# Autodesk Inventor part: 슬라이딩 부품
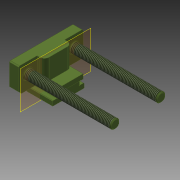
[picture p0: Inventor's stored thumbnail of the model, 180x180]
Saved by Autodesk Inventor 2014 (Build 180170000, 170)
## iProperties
Created: 2017-04
Part Number: 슬라이딩 부품
Material: 강철, 연강
Document SubType Name: Modeling
Designer: mduedu
Density: 7.86 g/cm^3
Appearance: 올리브 녹색
Mass: 390.322 g
Surface Area: 152.125 cm^2
Volume: 49.6593 cm^3
Author: mduedu
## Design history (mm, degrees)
sketch "스케치1"
  geometry: L1 (37, 35)-(10, 35); L2 (0, 17)-(0, 0); L3 (0, 17)-(5, 17); L4 (5, 17)-(5, 12); L5 (5, 12)-(10, 12); L6 (10, 12)-(10, 35); L7 (37, 35)-(37, 0); L8 (37, 0)-(0, 0); L9 (37, -35)-(10, -35); L10 (0, -17)-(0, 0); L11 (0, -17)-(5, -17); L12 (5, -17)-(5, -12); L13 (5, -12)-(10, -12); L14 (10, -12)-(10, -35); L15 (37, -35)-(37, 0)
  constraints: 30 end point, 6 symmetric about line, 3 perpendicular, 2 horizontal, 2 point on line, 2 vertical
  dimensions: "d39" = 5 distance of L2.start L3.end; "d41" = 70 distance between parallel lines of L9 L1; "d42" = 27 distance of L9.start L9.end; "d43" = 24 distance between parallel lines of L13 L5; "d44" = 5 distance of L4.end L5.end; "d45" = 34 distance between parallel lines of L11 L3
extrude "돌출1" new body sketch "스케치1" distance "d5" = 10; taper "d6" = 0 deg
sketch "스케치2"
  geometry: L1 (-35, 10)-(-35, 37) reference; L2 (17, 0)-(-17, 0) reference; L3 (-17, 0)-(-17, 5) reference; L4 (-17, 5)-(-12, 5) reference; L5 (-12, 5)-(-12, 10) reference; L6 (-12, 10)-(-35, 10) reference; L7 (-35, 37)-(35, 37) reference; L8 (35, 37)-(35, 10) reference; L9 (35, 10)-(12, 10) reference; L10 (12, 10)-(12, 5) reference; L11 (12, 5)-(17, 5) reference; L12 (17, 5)-(17, 0) reference; L13 (-12, 10)-(-15, 10); L14 (-15, 10)-(-15, 15); L15 (-15, 15)-(15, 15); L16 (15, 15)-(15, 10); L17 (15, 10)-(12, 10)
  constraints: 10 end point, 4 perpendicular, 2 point on line
  dimensions: "d46" = 3 distance between parallel lines of L14 L5; "d47" = 3 distance between parallel lines of L16 L10 (= d46); "d48" = 5 distance of L13.end L14.end
extrude "돌출2" join sketch "스케치2" distance "d12" = 20; taper "d13" = 0 deg
sketch "스케치3"
  geometry: L1 (0, 20)-(8, 20); L2 (8, 20)-(8, 50); L3 (8, 50)-(0, 50); L4 (0, 50)-(0, 20); L5 (0, 50)-(20, 50) reference; L6 (0, 20)-(20, 20) reference; L7 (0, 0)-(0, 70) reference; 2 further points
  constraints: 8 end point, 2 midpoint, 2 parallel, 1 horizontal, 1 perpendicular, 1 point on line
  dimensions: "d14" = 8 distance between parallel lines of L2 L4
extrude "돌출3" join sketch "스케치3" stored distance "d16" = 20; taper "d17" = 0 deg
fillet "모깎기1" dims "d18" = 5
sketch "스케치4"
  geometry: L1 (-15, 10)-(-35, 10) reference; L2 (-35, 10)-(-35, 37) reference; C1 r 5 at (-25, 25); 1 further point
  constraints: 1 centre point
  dimensions: "d19" = 10 diameter of C1; "d23" = 25 horizontal distance of point (0, 0) C1.centre (derived); "d49" = 15 distance from line of C1.centre L1; "d50" = 10 distance from line of C1.centre L2
extrude "돌출4" join sketch "스케치4" distance "d24" = 95; taper "d25" = 0 deg
feature "스레드1" dims "d26" = 10, "d27" = 0
chamfer "모따기1" distance "d28" = 1; stored, may be unused: second distance "d29" = 2, angle "d30" = 45 deg
fillet "모깎기2" dims "d31" = 1
sketch "스케치5"
  geometry: L1 (-12, 5)-(-12, 10) reference; L2 (12, 10)-(12, 5) reference; C1 r 0.5 at (-12, 10); C2 r 0.5 at (-12, 5); C3 r 0.5 at (12, 5); C4 r 0.5 at (12, 10); 1 further point
  constraints: 4 centre point, 4 coincident, 3 equal radius
  dimensions: "d51" = 1 diameter of C1
extrude "돌출5" cut sketch "스케치5" stored distance "d34" = 89; taper "d35" = 0 deg
chamfer "모따기2" distance "d36" = 3; stored, may be unused: second distance "d37" = 2, angle "d38" = 45 deg
chamfer "모따기3" distance "d52" = 0.5; stored, may be unused: second distance "d53" = 2, angle "d54" = 45 deg
sketch "스케치6"
  geometry: L1 (16.5, 5)-(17, 4.5) reference; L2 (16.5, 5)-(12.5, 5) reference; L3 (12, 5.5)-(12, 9.5) reference; L4 (-32, 10)-(-12.5, 10) reference; L5 (-12, 9.5)-(-12, 5.5) reference; L6 (-12.5, 5)-(-16.5, 5) reference; L7 (-17, 4.5)-(-16.5, 5) reference; L8 (-17, 4.5)-(-17, 0) reference; L9 (-17, 0)-(17, 0) reference; L10 (17, 0)-(17, 4.5) reference; L11 (11.5, 10)-(-11.5, 10); L12 (16.5, 5)-(17, 4.5) reference; L13 (16.5, 5)-(12.5, 5) reference; L14 (12, 5.5)-(12, 9.5) reference; L15 (12.5, 10)-(32, 10) reference; L16 (35, 13)-(32, 10) reference; L17 (35, 13)-(35, 36) reference; L18 (34, 37)-(-34, 37) reference; L19 (-35, 36)-(-35, 13) reference; L20 (-32, 10)-(-35, 13) reference; L21 (-32, 10)-(-12.5, 10) reference; L22 (-12, 9.5)-(-12, 5.5) reference; L23 (-12.5, 5)-(-16.5, 5) reference; L24 (-17, 4.5)-(-16.5, 5) reference; L25 (-17, 4.5)-(-17, 0) reference; L26 (-17, 0)-(17, 0) reference; L27 (17, 0)-(17, 4.5) reference; L28 (11.5, 5)-(-11.5, 5); L29 (34, 37)-(35, 36) reference; L30 (-35, 36)-(-34, 37) reference; A1 r 0.5 centre (12, 5) between (12, 5.5) and (12.5, 5) reference; A2 r 0.5 centre (12, 10) between (12.5, 10) and (12, 9.5) reference; A3 r 0.5 centre (-12, 10) between (-12, 9.5) and (-12.5, 10) reference; A4 r 0.5 centre (-12, 5) between (-12.5, 5) and (-12, 5.5) reference; A5 r 0.5 centre (12, 5) between (12, 5.5) and (12.5, 5) reference; A6 r 0.5 centre (12, 10) between (12.5, 10) and (12, 9.5) reference; A7 r 0.5 centre (-12, 10) between (-12, 9.5) and (-12.5, 10) reference; A8 r 0.5 centre (-12, 5) between (-12.5, 5) and (-12, 5.5) reference; 1 further point
  constraints: 4 end point, 4 point on circle, 2 collinear, 2 perpendicular
extrude "돌출6" cut sketch "스케치6" distance "d55" = 1; taper "d56" = 0 deg
node "작업 평면1"
sketch "스케치7"
  geometry: C1 r 4.2 at (-23, 25.5) reference; C2 r 4.2 at (23, 25.5) reference; 3 further points
  constraints: 2 coincident
hole "구멍1" sketch "스케치7" at (-23, 25.5), (23, 25.5) diameter "d57" = 3.242; stored, may be unused: countersink angle "d61" = 90 deg, drill point angle "d63" = 118 deg; dims "d58" = 6, "d59" = 4, "d60" = 2, "d62" = 8
mirror "대칭2"
mirror "대칭3"
node "솔리드2"
node "투영된 루프1"
node "투영된 루프2"
node "참조1"
node "참조2"
node "솔리드1"
